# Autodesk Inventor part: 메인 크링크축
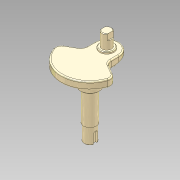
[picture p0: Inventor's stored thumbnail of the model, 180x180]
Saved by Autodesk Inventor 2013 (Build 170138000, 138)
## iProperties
Manager: KYOUNG IL JANG
Company: 한국ATC센터
Created: 2012-10
Part Number: 메인 크링크축
Document SubType Name: Modeling
Density: 1 g/cm^3
Checked By: KYOUNG IL JANG
Vendor: CBT Solutions
Designer: KYOUNG IL JANG
Material: 일반
크링크폭: 19.000 mm
크랭크길이: 18.000 mm
크랭키위치: 65.000 mm
무게추: 90.000 mm
크랭크각도높이: 21.000 mm
크링크각도: -15.00 deg
Author: KYOUNG IL JANG
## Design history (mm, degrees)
sketch "스케치1"
  geometry: L1 (-19, 109.368)-(-19, 91.368); L2 (-19, 91.368)-(-44.545, 76.619); L3 (19, 109.368)-(19, 91.368); L4 (19, 91.368)-(44.545, 76.619); C1 r 32.5 at (0, 83) reference; C2 r 10 at (0, 83); C3 r 17.5 at (0, 83); A1 r 45 centre (0, 83) between (-44.545, 76.619) and (44.545, 76.619); A2 r 32.5 centre (0, 83) between (-19, 109.368) and (19, 109.368); A3 r 19 centre (0, 109.368) between (19, 109.368) and (-19, 109.368); 1 further point
  constraints: 8 end point, 6 point on circle, 5 centre point, 4 coincident, 2 equal length, 2 vertical alignment, 1 horizontal alignment, 1 parallel, 1 tangent, 1 vertical, 3 other
  dimensions: "d0" = 20 diameter of C2; "d1" = 35 diameter of C3; "d4" = 120 deg angle of L3 L4
  node "참조1"
extrude "돌출1" new body sketch "스케치1" distance "d7" = 12; taper "d8" = 0 deg
extrude "돌출2" join sketch "스케치1" distance "d9" = 5; taper "d10" = 0 deg
extrude "돌출3" join sketch "스케치1" distance "d11" = 100; taper "d12" = 0 deg
sketch "스케치2"
  geometry: C1 r 7.5 at (0, 109.368); C2 r 11 at (0, 109.368); A1 r 19 centre (0, 109.368) between (19, 109.368) and (-19, 109.368) reference; 1 further point
  constraints: 2 centre point, 2 coincident
  dimensions: "d13" = 15 diameter of C1; "d14" = 22 diameter of C2
extrude "돌출4" join sketch "스케치2" distance "d15" = 3; taper "d16" = 0 deg
extrude "돌출5" join sketch "스케치2" distance "d17" = 25; taper "d18" = 0 deg
node "작업 평면1"
sketch "스케치3"
  geometry: L1 (-5.75, 4.815)-(-5.75, -4.815); L2 (5.75, 4.815)-(5.75, -4.815); A1 r 7.5 centre (0, 0) between (-5.75, 4.815) and (-5.75, -4.815) reference; 1 further point
  constraints: 4 end point, 4 point on circle, 2 parallel, 1 vertical
  dimensions: "d20" = 11.5 distance between parallel lines of L2 L1
extrude "돌출6" cut sketch "스케치3" stored distance "d21" = 10; taper "d22" = 0 deg
sketch "스케치4"
  geometry: L1 (-19, 91.368)-(-19, 109.368) reference; L2 (19, 109.368)-(19, 91.368) reference; C1 r 17.5 at (0, 83) reference; 3 further points
  constraints: 2 point on line, 1 horizontal alignment, 1 other
node "작업 평면2"
  node "작업축1"
sketch "스케치5"
  geometry: L1 (0, 0)-(38, 0); L2 (38, 0)-(38, 50); L3 (38, 50)-(0, 50); L4 (0, 50)-(0, 0); L5 (38, 5.185)-(38, -12.202) reference; 2 further points
  constraints: 8 end point, 1 coincident, 1 collinear, 1 horizontal, 1 perpendicular
  dimensions: "d27" = 50 distance between parallel lines of L3 L1
extrude "돌출7" cut sketch "스케치5" stored distance "d28" = 10; taper "d29" = 0 deg
fillet "모깎기1" dims "d23" = 10, "d24" = 2
sketch "스케치6"
  geometry: C1 r 17.5 at (0, 0) reference; C2 r 15 at (0, 0); 1 further point
  constraints: 1 centre point, 1 coincident
  dimensions: "d30" = 30 diameter of C2
extrude "돌출8" join sketch "스케치6" distance "d31" = 21; taper "d32" = 0 deg
sketch "스케치7"
  geometry: C1 r 10 at (0, 0) reference; C2 r 9 at (0, 0); 1 further point
  constraints: 1 centre point, 1 coincident
  dimensions: "d33" = 1 radial gap between concentric circles of C1 C2
extrude "돌출9" cut sketch "스케치7" distance "d34" = 25; taper "d35" = 0 deg
node "작업 평면3"
sketch "스케치8"
  geometry: L1 (-9, 0)-(9, 0) reference; L2 (-3, 0)-(-3, 15); L3 (3, 15)-(3, 0); A1 r 3 centre (0, 15) between (3, 15) and (-3, 15); 2 further points
  constraints: 4 end point, 2 perpendicular, 2 point on circle, 2 point on line, 2 tangent, 1 centre point, 1 midpoint, 1 vertical alignment
  dimensions: "d36" = 6 distance between parallel lines of L3 L2; "d37" = 18 dimension on A1 L1
extrude "돌출10" cut sketch "스케치8" distance "d38" = 3.5; taper "d39" = 0 deg
chamfer "모따기1" distance "d40" = 1; stored, may be unused: second distance "d41" = 2, angle "d42" = 45 deg
node "솔리드1"
node "투영된 루프1"
other parameters: "d19" = 13
